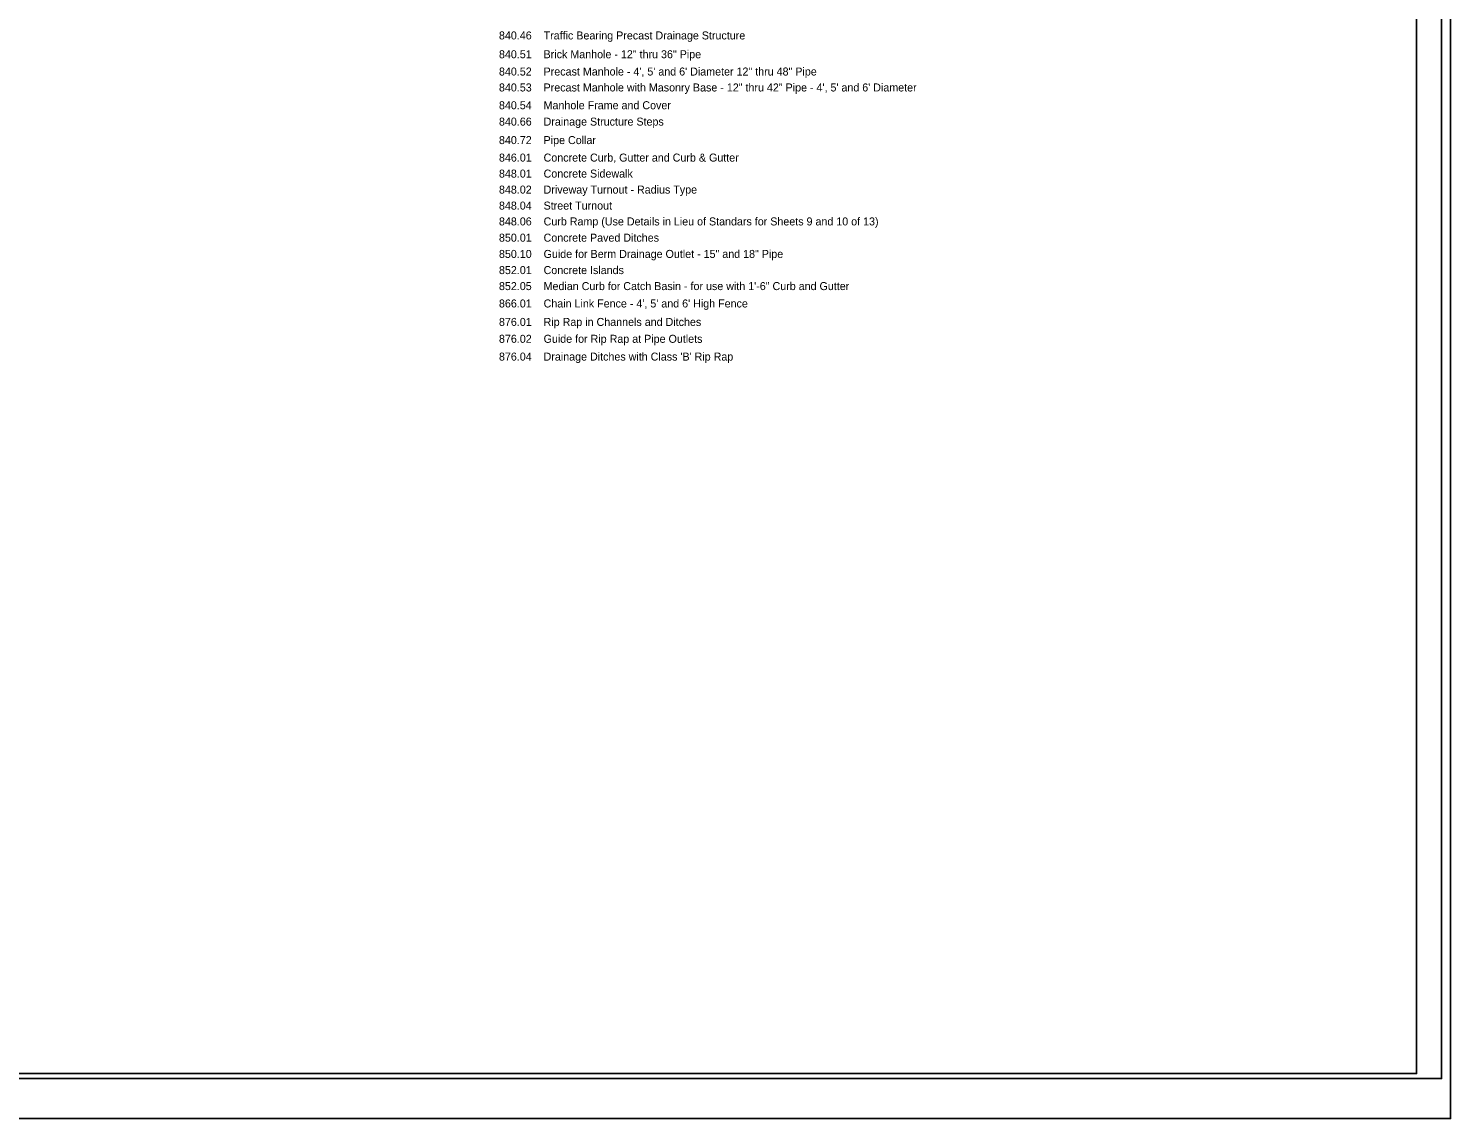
# Model space of a CAD drawing. Extents: x 1537922 to 1539606, y 409903 to 410998.
# Drawn here: x 1538895 to 1539606, y 409903 to 410448 of the extents above; entities that cross this region are included whole.
import ezdxf

# ---------------------------------------------------------------- set-up
doc = ezdxf.new("R2010")
doc.units = 0
for name, color, linetype in [('Default', 7, 'Continuous'), ('Sheet Cutting Line CELL', 7, 'Continuous'), ('Sheet Plan CELL', 7, 'Continuous'), ('Sheet Plot Border Inside CELL', 7, 'Continuous'), ('Sheet Plot Border Outside CELL', 7, 'Continuous')]:
    doc.layers.add(name, color=color, linetype=linetype)

msp = doc.modelspace()

# ---------------------------------------------------------------- linework, layer by layer
at = {"layer": 'Sheet Cutting Line CELL'}
msp.add_line((1537922.37, 409903.35), (1539605.87, 409903.35), dxfattribs=at)
at = {"layer": 'Sheet Plan CELL'}
msp.add_lwpolyline([(1539588.87, 410975.85), (1538088.87, 410975.85), (1538088.87, 409925.85), (1539588.87, 409925.85)], close=True, dxfattribs=at)
at = {"layer": 'Sheet Plot Border Inside CELL'}
msp.add_lwpolyline([(1537935.37, 409923.35), (1539601.37, 409923.35), (1539601.37, 410978.35), (1537935.37, 410978.35)], close=True, dxfattribs=at)
at = {"layer": 'Sheet Plot Border Outside CELL'}
msp.add_lwpolyline([(1537922.37, 409903.35), (1539605.87, 409903.35), (1539605.87, 410998.35), (1537922.37, 410998.35)], close=True, dxfattribs=at)

# ---------------------------------------------------------------- texts
at = {"layer": 'Default'}
for s, p in [('840.46    Traffic Bearing Precast Drainage Structure', (1539130.32, 410442.89)), ('840.51    Brick Manhole - 12" thru 36" Pipe', (1539130.32, 410433.49)), ('840.52    Precast Manhole - 4\', 5\' and 6\' Diameter 12" thru 48" Pipe', (1539130.32, 410424.85)), ('840.53    Precast Manhole with Masonry Base - 12" thru 42" Pipe - 4\', 5\' and 6\' Diameter', (1539130.32, 410416.88)), ('840.54    Manhole Frame and Cover', (1539130.32, 410407.99)), ('840.66    Drainage Structure Steps', (1539130.32, 410399.81)), ('840.72    Pipe Collar', (1539130.32, 410390.57)), ('846.01    Concrete Curb, Gutter and Curb & Gutter', (1539130.32, 410381.82)), ('848.01    Concrete Sidewalk', (1539130.32, 410373.82)), ('848.02    Driveway Turnout - Radius Type', (1539130.32, 410365.82)), ('848.04    Street Turnout', (1539130.32, 410357.82)), ('848.06    Curb Ramp (Use Details in Lieu of Standars for Sheets 9 and 10 of 13)', (1539130.32, 410349.9)), ('850.01    Concrete Paved Ditches', (1539130.32, 410341.78)), ('850.10    Guide for Berm Drainage Outlet - 15" and 18" Pipe', (1539130.32, 410333.65)), ('852.01    Concrete Islands', (1539130.32, 410325.57)), ('852.05    Median Curb for Catch Basin - for use with 1\'-6" Curb and Gutter', (1539130.32, 410317.57)), ("866.01    Chain Link Fence - 4', 5' and 6' High Fence", (1539130.32, 410308.88)), ('876.01    Rip Rap in Channels and Ditches', (1539130.32, 410299.65)), ('876.02    Guide for Rip Rap at Pipe Outlets', (1539130.32, 410291.21)), ("876.04    Drainage Ditches with Class 'B' Rip Rap", (1539130.32, 410282.32))]:
    msp.add_text(s, height=4, dxfattribs=at).set_placement(p)

doc.saveas('drawing.dxf')
